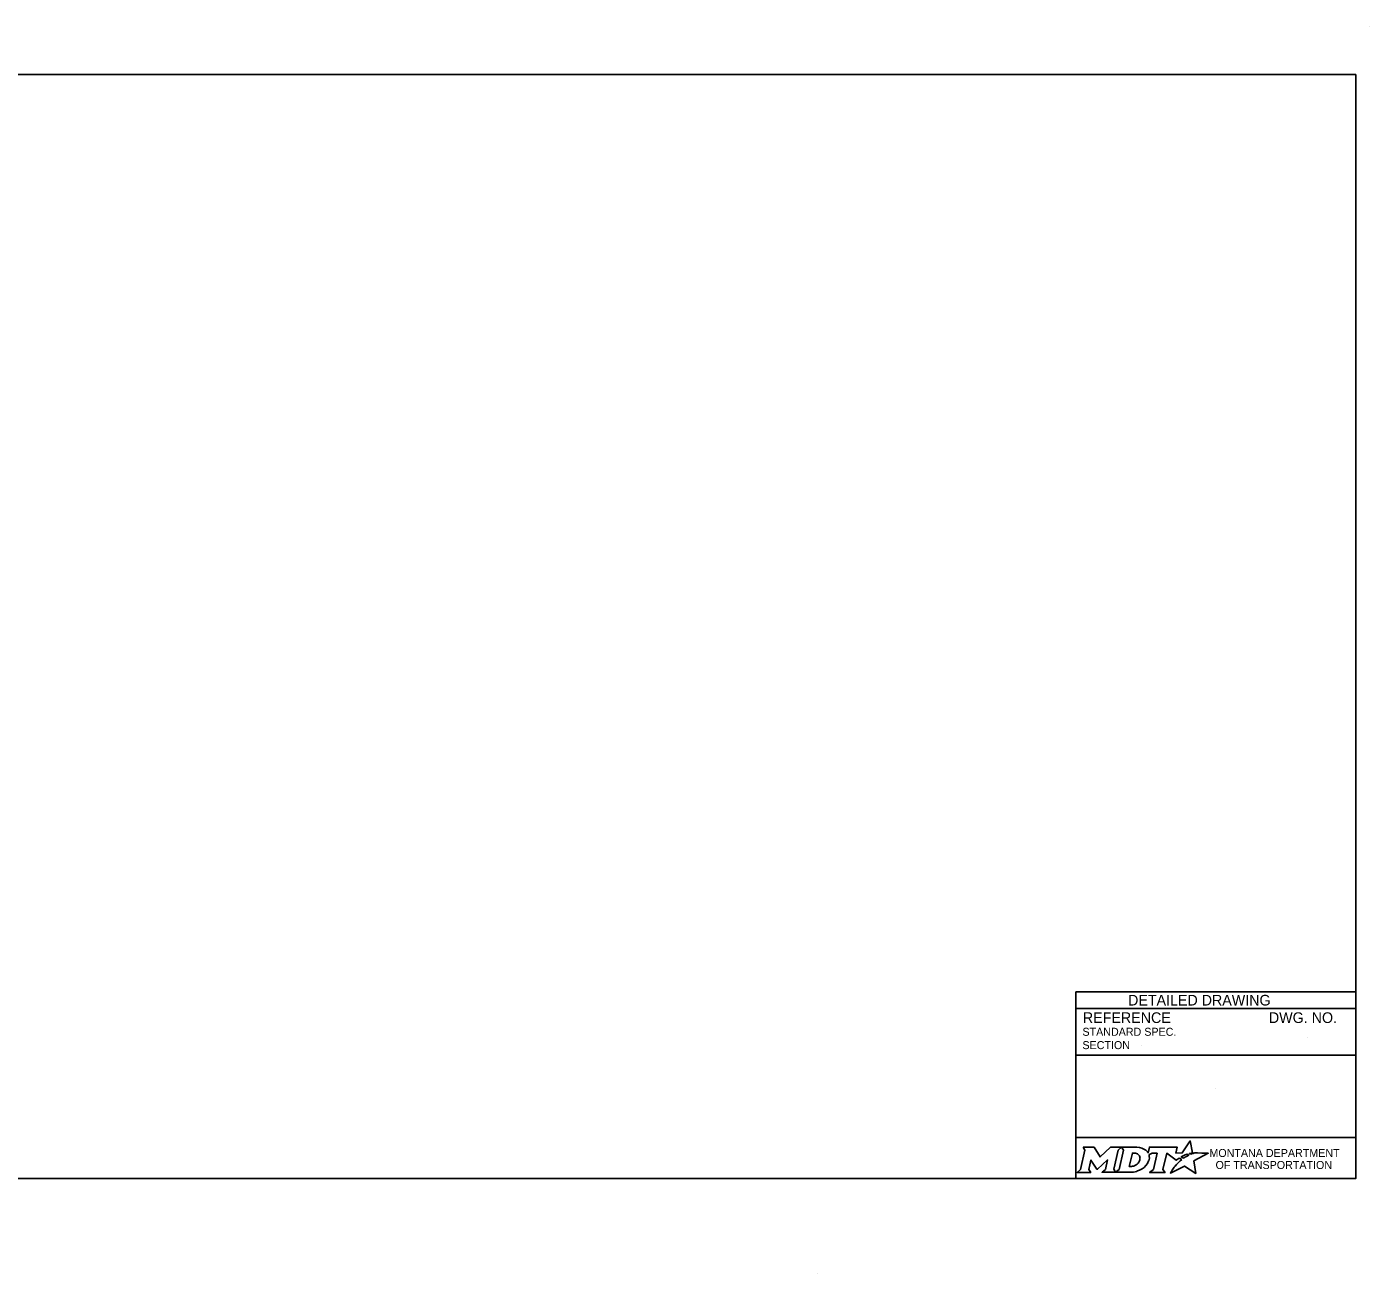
# Model space of a CAD drawing. Extents: x 49991 to 50160, y 49948 to 50051.
# Drawn here: x 50010.97 to 50021.04, y 49999.18 to 50008.52 of the extents above; entities that cross this region are included whole.
import ezdxf

# ---------------------------------------------------------------- set-up
doc = ezdxf.new("R2010")
doc.units = 0
for name, color, linetype in [('Default', 7, 'Continuous'), ('Level 1', 7, 'Continuous'), ('Level 4', 7, 'Continuous')]:
    doc.layers.add(name, color=color, linetype=linetype)

msp = doc.modelspace()

# ---------------------------------------------------------------- linework, layer by layer
at = {"layer": 'Default'}
for points in [[(50019.7, 50000.068), (50019.69, 50000.074), (50019.702, 50000.076), (50019.713, 50000.078), (50019.696, 50000.168), (50019.636, 50000.077), (50019.589, 50000.076), (50019.599, 50000.12), (50019.39, 50000.121), (50019.38, 50000.078), (50019.374, 50000.086)], [(50018.893, 50000.121), (50018.907, 50000.097), (50018.874, 49999.954), (50018.848, 49999.931), (50018.95, 49999.931), (50018.936, 49999.954), (50018.952, 50000.024), (50018.996, 49999.955), (50019.002, 49999.955), (50019.077, 50000.025), (50019.06, 49999.954), (50019.035, 49999.932), (50019.137, 49999.932), (50019.123, 49999.955), (50019.156, 50000.097)], [(50019.156, 50000.097), (50019.182, 50000.121), (50019.099, 50000.121), (50019.02, 50000.048), (50018.975, 50000.12), (50018.893, 50000.121)], [(50019.295, 50000.121), (50019.182, 50000.121), (50019.196, 50000.098), (50019.163, 49999.954), (50019.137, 49999.932), (50019.248, 49999.932)], [(50019.319, 50000.034), (50019.318, 50000.026), (50019.315, 50000.017), (50019.311, 50000.008), (50019.305, 50000.001), (50019.299, 49999.994), (50019.291, 49999.988), (50019.282, 49999.983), (50019.273, 49999.979), (50019.264, 49999.977), (50019.255, 49999.976), (50019.239, 49999.976), (50019.263, 50000.076), (50019.279, 50000.076), (50019.286, 50000.075), (50019.294, 50000.073), (50019.301, 50000.07), (50019.307, 50000.066), (50019.311, 50000.061), (50019.315, 50000.055), (50019.318, 50000.049), (50019.319, 50000.042), (50019.32, 50000.038), (50019.319, 50000.034)], [(50019.387, 50000.062), (50019.411, 50000.075), (50019.448, 50000.075), (50019.42, 49999.954), (50019.392, 49999.931), (50019.508, 49999.931), (50019.491, 49999.954), (50019.52, 50000.075), (50019.591, 50000.023), (50019.612, 50000.038), (50019.632, 50000.027)], [(50019.576, 49999.971), (50019.561, 49999.947), (50019.556, 49999.939), (50019.55, 49999.931), (50019.548, 49999.926), (50019.653, 49999.979), (50019.737, 49999.924), (50019.724, 50000.017), (50019.831, 50000.075), (50019.782, 50000.076), (50019.751, 50000.077), (50019.731, 50000.077), (50019.724, 50000.075), (50019.719, 50000.074), (50019.711, 50000.072), (50019.7, 50000.068)], [(50019.65, 50000.04), (50019.648, 50000.039), (50019.629, 50000.048), (50019.639, 50000.054), (50019.644, 50000.056), (50019.652, 50000.06), (50019.658, 50000.063), (50019.666, 50000.066), (50019.673, 50000.068), (50019.685, 50000.061), (50019.681, 50000.059), (50019.676, 50000.056), (50019.672, 50000.054), (50019.667, 50000.051), (50019.665, 50000.05), (50019.662, 50000.049), (50019.66, 50000.047), (50019.658, 50000.046), (50019.655, 50000.044), (50019.652, 50000.042), (50019.65, 50000.04)], [(50019.59, 49999.987), (50019.59, 49999.987)], [(50019.293, 49999.939), (50019.302, 49999.942), (50019.315, 49999.947), (50019.335, 49999.958)]]:
    msp.add_lwpolyline(points, dxfattribs=at)
for centre, radius, start, end in [((50019.274, 50000.059), 0.118, 300.9103, 339.1383), ((50019.319, 50000.042), 0.0709, 339.5329, 15.8582)]:
    msp.add_arc(centre, radius, start, end, dxfattribs=at)
for centre, major_axis, ratio, start_param, end_param in [((50019.293, 50000.073), (0.0834, -0.0037), 0.568097, 0.61298, 1.570796), ((50019.349, 50000.081), (0.0361, -0.0295), 0.469099, 1.225588, 1.570796), ((50019.583, 49999.979), (-0.00694, -0.00806), 0.008222, 0, 3.137361), ((50019.6, 49999.997), (-0.0098, -0.0102), 0.016458, 3.141593, 6.279097), ((50019.621, 50000.017), (-0.0112, -0.0097), 0.021651, 3.157348, 6.283185), ((50019.248, 50000.08), (0, 0.148), 0.987302, 3.139398, 3.456847)]:
    msp.add_ellipse(centre, major_axis=major_axis, ratio=ratio, start_param=start_param, end_param=end_param, dxfattribs=at)
at = {"layer": 'Level 1'}
for p, q in [((50021.038, 50008.524), (50021.038, 50008.524)), ((50016.9, 49999.176), (50016.9, 49999.176))]:
    msp.add_line(p, q, dxfattribs=at)
msp.add_lwpolyline([(50020.938, 50008.165), (50009.737, 50008.165), (50009.737, 49999.886), (50020.938, 49999.886)], close=True, dxfattribs=at)
at = {"layer": 'Level 4'}
for p, q in [((50020.938, 50001.286), (50018.838, 50001.286)), ((50018.838, 50001.286), (50018.838, 49999.886)), ((50020.938, 50001.161), (50018.838, 50001.161)), ((50019.332, 50000.886), (50019.332, 50000.886)), ((50020.574, 50000.946), (50020.574, 50000.946)), ((50020.938, 50000.811), (50018.838, 50000.811)), ((50019.888, 50000.562), (50019.888, 50000.562)), ((50020.938, 50000.193), (50018.838, 50000.193))]:
    msp.add_line(p, q, dxfattribs=at)

# ---------------------------------------------------------------- texts
at = {"layer": 'Default'}
for s, p in [('MONTANA DEPARTMENT', (50019.84, 50000.047)), ('OF TRANSPORTATION', (50019.886, 49999.957))]:
    msp.add_text(s, height=0.06, rotation=360, dxfattribs=at).set_placement(p)
at = {"layer": 'Level 4'}
for s, height, p in [('DETAILED DRAWING', 0.0799, (50019.23, 50001.183)), ('REFERENCE', 0.08, (50018.891, 50001.052)), ('DWG. NO.', 0.08, (50020.286, 50001.052)), ('STANDARD SPEC.', 0.06, (50018.888, 50000.956)), ('SECTION', 0.06, (50018.888, 50000.856))]:
    msp.add_text(s, height=height, dxfattribs=at).set_placement(p)

doc.saveas('drawing.dxf')
